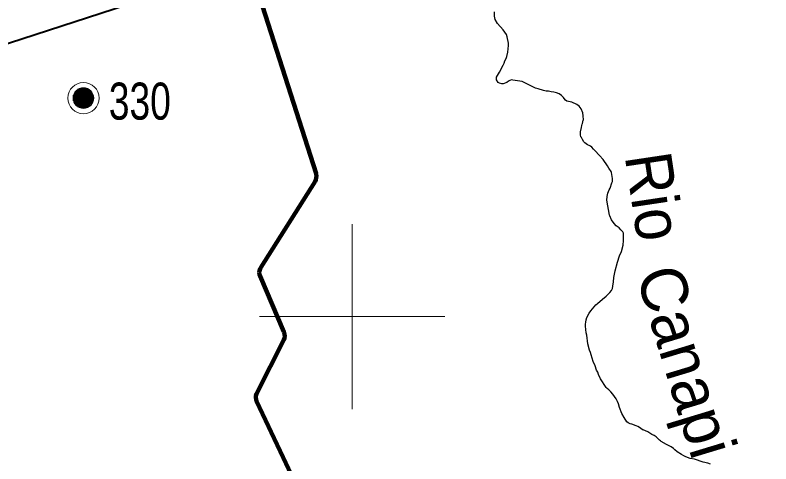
# Model space of a CAD drawing. Extents: x 553962 to 842807, y 8883888 to 9032388.
# Drawn here: x 646361 to 654521, y 8973410 to 8978256 of the extents above; entities that cross this region are included whole.
import ezdxf
from ezdxf.enums import TextEntityAlignment as Align

# ---------------------------------------------------------------- set-up
doc = ezdxf.new("R2010")
doc.units = 0
doc.header["$LTSCALE"] = 160
doc.linetypes.add('DOT_DASHED', pattern=[7.7, 5, -1.2, 0.3, -1.2])
for name, color, linetype, lineweight in [('1', 7, 'Continuous', 13), ('15', 7, 'Continuous', 25), ('21', 7, 'Continuous', 25), ('22', 7, 'Continuous', 35), ('33', 7, 'Continuous', 13), ('7', 7, 'Continuous', 90)]:
    doc.layers.add(name, color=color, linetype=linetype, lineweight=lineweight)

msp = doc.modelspace()

# ---------------------------------------------------------------- linework, layer by layer
at = {"layer": '1'}
for p, q in [((650000, 8974000), (650000, 8976000)), ((649000, 8975000), (651000, 8975000))]:
    msp.add_line(p, q, dxfattribs=at)
at = {"layer": '15', "lineweight": 40}
msp.add_line((636526.5, 8974783.6), (662912, 8983353), dxfattribs=at)
at = {"layer": '21'}
for points in [[(652489.3, 8977200.8), (652471.2, 8977244.5), (652451.6, 8977272.3), (652426.7, 8977289.8), (652372.7, 8977314.7), (652316.8, 8977327.6), (652304, 8977338.4), (652290, 8977356.2), (652282.8, 8977367.6), (652261.2, 8977388.3), (652233.5, 8977404.6), (652205.7, 8977416.4), (652176.2, 8977425.4), (652149.3, 8977428.7), (652121.4, 8977433.9), (652093.6, 8977436.2), (652067.6, 8977441.1), (652008.3, 8977458.1), (651980.6, 8977468), (651871, 8977521.8), (651837.3, 8977540.6), (651735.9, 8977553.5), (651721.5, 8977558), (651704.1, 8977550.5), (651687.1, 8977541), (651670, 8977527.3), (651631.1, 8977514.4), (651617.8, 8977514.2), (651591.8, 8977520.8), (651576.4, 8977529), (651559.7, 8977556.6), (651560.3, 8977586.9), (651590.6, 8977638.4), (651629.2, 8977716.5), (651642.5, 8977738.3), (651649.6, 8977762.4), (651662.8, 8977787.8), (651669.7, 8977809.6), (651669.7, 8977809.6), (651681.5, 8977856.7), (651689, 8977928.2), (651688.8, 8977951.7), (651675, 8978021.5), (651664.7, 8978046.3), (651630.7, 8978095), (651568.9, 8978165.5), (651544.2, 8978209), (651538.3, 8978244.1), (651537.2, 8978289.4)], [(652799.8, 8975280.4), (652799.8, 8975280.4), (652809.8, 8975302.2), (652816.1, 8975328.3), (652822.4, 8975374.6), (652826.9, 8975422.5), (652839.8, 8975493.2), (652864.5, 8975587.5), (652888.2, 8975655.6), (652908, 8975704.5), (652925.9, 8975773.4), (652929.4, 8975820.5), (652930.5, 8975902.1), (652923, 8975914.4), (652902.1, 8975937.5), (652881.4, 8975957.1), (652852.2, 8975978.9), (652827.9, 8976005.5), (652801.9, 8976045.7), (652783.3, 8976090.1), (652777.5, 8976093.8), (652748.7, 8976257.8), (652752.2, 8976297.8), (652759.6, 8976332.9), (652774.2, 8976369.2), (652784.3, 8976387.2), (652805.5, 8976443.3), (652809.5, 8976460.7), (652811.3, 8976493), (652801.1, 8976555.8), (652798.8, 8976558), (652796.5, 8976566.6), (652771.4, 8976603.6), (652757.2, 8976628.1), (652709.4, 8976696.7), (652669.3, 8976741.1), (652619.4, 8976792.3), (652606, 8976809.7), (652586.7, 8976830.1), (652573.9, 8976839.8), (652558.6, 8976848.9), (652539.4, 8976855.7), (652512.1, 8976876), (652503.2, 8976887), (652485.9, 8976913.6), (652475.6, 8976934.7), (652470.3, 8976940.8), (652464.8, 8976961.4), (652465.9, 8976994), (652475.8, 8977041.9), (652478.7, 8977062.5), (652483.1, 8977079.2), (652486.9, 8977086.7), (652487.3, 8977094.1), (652489.3, 8977098.5), (652490.4, 8977112.9), (652494.6, 8977117.7), (652496.8, 8977124.6), (652495.6, 8977167.5), (652489.3, 8977200.8)], [(653869.2, 8973406.6), (653838.8, 8973418.7), (653790.9, 8973428.7), (653697.5, 8973459.4), (653649.6, 8973468.4), (653604, 8973484.9), (653582.4, 8973495.6), (653556.1, 8973510.9), (653509.5, 8973541.4), (653482.9, 8973561.9), (653470.5, 8973577.6), (653442.6, 8973592.3), (653395.4, 8973620.1), (653335.2, 8973650.9), (653328.8, 8973657.6), (653317.1, 8973665.3), (653282.9, 8973700.4), (653261.2, 8973715), (653237, 8973727.3), (653213.3, 8973743.3), (653191.4, 8973755.3), (653143.5, 8973777.1), (653134.4, 8973779.3), (653111.9, 8973795.2), (653085.1, 8973811.8), (653065.5, 8973821.4), (653019.2, 8973837.3), (653002.9, 8973840.6), (652981, 8973851.6), (652965.9, 8973864.6), (652937, 8973909.3), (652911.1, 8973953), (652887.5, 8974017.3), (652874.5, 8974060.1), (652864.8, 8974083.7), (652850.2, 8974112.8), (652813.3, 8974163.9), (652794.5, 8974187.8), (652771, 8974210.2), (652753.5, 8974223.6), (652741.1, 8974236.2), (652681.1, 8974329.2), (652660, 8974375.6), (652651, 8974399.9), (652639.3, 8974423.5), (652623.5, 8974469.8), (652603.2, 8974516.9), (652579.3, 8974588.4), (652572.8, 8974612), (652562.8, 8974637.3), (652546.2, 8974706.2), (652532.2, 8974799.6), (652526.8, 8974824.9), (652519.2, 8974897.6), (652518.3, 8974918.3), (652521.3, 8974941), (652527.4, 8974967.1), (652535.4, 8974989), (652558, 8975036.1), (652577.2, 8975063.9), (652631.7, 8975125.9), (652648.1, 8975141.2), (652704.5, 8975187.2), (652741, 8975221.5), (652762.8, 8975244.2), (652783.3, 8975259.7), (652799.8, 8975280.4)]]:
    msp.add_lwpolyline(points, dxfattribs=at)
at = {"layer": '33'}
for p, q in [((646999, 8977410), (646999, 8977310)), ((647009, 8977430), (647009, 8977290)), ((647019, 8977440), (647019, 8977280)), ((647029, 8977450), (647029, 8977270)), ((647039, 8977460), (647039, 8977260)), ((647049, 8977460), (647049, 8977260)), ((647059, 8977460), (647059, 8977260)), ((647069, 8977470), (647069, 8977250)), ((647079, 8977470), (647079, 8977250)), ((647089, 8977470), (647089, 8977250)), ((647099, 8977470), (647099, 8977250)), ((647109, 8977470), (647109, 8977250)), ((647119, 8977470), (647119, 8977250)), ((647129, 8977470), (647129, 8977250)), ((647139, 8977460), (647139, 8977260)), ((647149, 8977460), (647149, 8977260)), ((647159, 8977450), (647159, 8977270)), ((647169, 8977440), (647169, 8977280)), ((647179, 8977430), (647179, 8977290)), ((647189, 8977420), (647189, 8977300)), ((646989, 8977390), (646989, 8977330)), ((647199, 8977400), (647199, 8977320))]:
    msp.add_line(p, q, dxfattribs=at)
for radius in [168.7, 111]:
    msp.add_circle((647099, 8977360), radius, dxfattribs=at)
at = {"layer": '7'}
for points in [[(648997.5, 8975475.9), (648999.4, 8975495.8), (649005.2, 8975514.9), (649012.9, 8975529.8), (649599.2, 8976460.8), (649608.1, 8976478.7), (649613.2, 8976498), (649614.5, 8976517.9), (649611.7, 8976537.7), (649609.8, 8976544.5), (648760.2, 8979209.5), (648756, 8979229.1), (648755.9, 8979249), (648759.7, 8979268.6), (648765.1, 8979282.8), (648947.1, 8979666.4)], [(648997.5, 8975475.9), (648999.4, 8975495.8), (649005.2, 8975514.9), (649012.9, 8975529.8), (649599.2, 8976460.8), (649608.1, 8976478.7), (649613.2, 8976498), (649614.5, 8976517.9), (649611.7, 8976537.7), (649609.8, 8976544.5), (648760.2, 8979209.5), (648756, 8979229.1), (648755.9, 8979249), (648759.7, 8979268.6), (648765.1, 8979282.8), (648947.1, 8979666.4)], [(649341.1, 8973293.8), (649254.1, 8973479.3), (648969, 8974087), (648962.3, 8974105.8), (648959.6, 8974125.6), (648960.8, 8974145.6), (648966, 8974164.9), (648970.3, 8974174.6), (649261.4, 8974750.4), (649268.6, 8974769), (649271.9, 8974788.7), (649271.3, 8974808.7), (649266.7, 8974828.1), (649264, 8974834.9), (649005.6, 8975437), (648999.6, 8975456.1), (648997.5, 8975475.9)]]:
    msp.add_lwpolyline(points, dxfattribs=at)
at = {"layer": '7', "linetype": 'DOT_DASHED'}
msp.add_lwpolyline([(649341.1, 8973293.8), (649254.1, 8973479.3), (648969, 8974087), (648962.3, 8974105.8), (648959.6, 8974125.6), (648960.8, 8974145.6), (648966, 8974164.9), (648970.3, 8974174.6), (649261.4, 8974750.4), (649268.6, 8974769), (649271.9, 8974788.7), (649271.3, 8974808.7), (649266.7, 8974828.1), (649264, 8974834.9), (649005.6, 8975437), (648999.6, 8975456.1), (648997.5, 8975475.9)], dxfattribs=at)

# ---------------------------------------------------------------- texts
at = {"layer": '22', "width": 0.95}
msp.add_text('Rio', height=500, rotation=278.527, dxfattribs=at).set_placement((653013, 8976261.9), align=Align.CENTER)
at = {"layer": '22'}
msp.add_text('Canapi', height=500, rotation=286.879, dxfattribs=at).set_placement((653368, 8974444.7), align=Align.CENTER)
at = {"layer": '33', "width": 0.75}
msp.add_text('330', height=400, dxfattribs=at).set_placement((647373.2, 8977127.1))

doc.saveas('drawing.dxf')
